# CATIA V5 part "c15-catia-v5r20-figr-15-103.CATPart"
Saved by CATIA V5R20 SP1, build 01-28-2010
Part number: Part1
Bounding box of the stored display mesh (mm): x -60.955 to 60.955, y -33.748 to 33.748, z 0 to 6.052
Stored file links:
  D:\v5_r20\psrt_files_downloaded\c15\c15-catia-v5r20-figr-15-103.CATPart
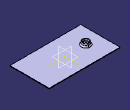
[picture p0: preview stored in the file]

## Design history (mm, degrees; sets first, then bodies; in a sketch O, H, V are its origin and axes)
SheetMetalParameters1: Thickness 1, BendRadius 5, KFactor 0.5 {= log(min(100,max(20*SheetMetalParameters1.BendRadius,SheetMetalParameters1.Thickness)/SheetMetalParameters1.Thickness))/log(100)/2}, ReliefRadialLength 1, ReliefAxialLength 2, MinimumBendRadius 0
Body1 (main body)
  Sketch1 on xy-plane, origin (0, 0, 0), H (1, 0, 0), V (0, 1, 0)
    line L1 (60.9549, 33.7477) -> (60.9549, -33.7477)
    line L2 (60.9549, -33.7477) -> (-60.9549, -33.7477)
    line L3 (-60.9549, -33.7477) -> (-60.9549, 33.7477)
    line L4 (-60.9549, 33.7477) -> (60.9549, 33.7477)
    vertical: L1 V, L3 V
    horizontal: L2 H, L4 H
    equidistance: L1 L3 O, L2 L4 O
  Wall1: Thickness 1, Profile Sketch1
  Sketch2 on face of Wall1, origin (0, 0, 1), H (1, 0, 0), V (0, 1, 0)
    point P1 (-35.8601, 0)
    coincidence: P1 H
  Sketch3 on face of Wall1, origin (-35.8601, 0, 1), H (1, 0, 0), V (0, 1, 0)
    point P1 (0, 0)
    reference projected point E1 (0, 0) from Sketch2.P1
    coincidence: E1 P1
  d_Stamp1: KFacteur 0.5 {= SheetMetalParameters1.KFactor}, Stamp_FilletRadius 2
